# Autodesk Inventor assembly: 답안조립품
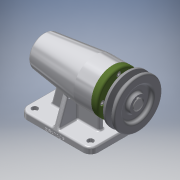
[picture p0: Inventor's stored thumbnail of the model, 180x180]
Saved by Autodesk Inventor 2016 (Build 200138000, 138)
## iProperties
Created: 2018-09
Part Number: 답안조립품
Document SubType Name: Assembly
Designer: CAMTIC
Author: CAMTIC
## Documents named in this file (12)
- C:\Users\CAMTIC\Desktop\480907V1020\답안조립품.iam
- C:\Users\CAMTIC\Desktop\480907V1020\본체.ipt
- C:\Users\CAMTIC\Desktop\480907V1020\커버.ipt
- C:\Users\CAMTIC\Desktop\480907V1020\볼트 M4.ipt
- C:\Users\CAMTIC\Desktop\480907V1020\베어링 6004.ipt
- C:\Users\CAMTIC\Desktop\480907V1020\축.ipt
- C:\Users\CAMTIC\Desktop\480907V1020\어댑터슬리브.ipt
- C:\Users\CAMTIC\Desktop\480907V1020\베어링 51202.ipt
- C:\Users\CAMTIC\Desktop\480907V1020\오일 실.ipt
- C:\Users\CAMTIC\Desktop\480907V1020\멈춤나사 M3.ipt
- C:\Users\CAMTIC\Desktop\480907V1020\키 5 x 5 x 16.ipt
- C:\Users\CAMTIC\Desktop\480907V1020\V벨트풀리.ipt
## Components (1 placed, 1 different names)
1. V벨트풀리:1 — Insert:11, Mate:8
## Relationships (2: Insert 1, Mate 1)
- Insert:11: V벨트풀리:1
- Mate:8: V벨트풀리:1
